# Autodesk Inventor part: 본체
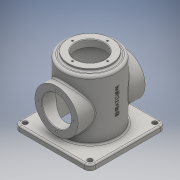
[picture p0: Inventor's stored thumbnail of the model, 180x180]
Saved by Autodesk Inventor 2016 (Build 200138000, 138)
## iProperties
Created: 2019-08
Part Number: 본체
Material: 일반
Document SubType Name: Modeling
Designer: user
Density: 1 g/cm^3
Appearance: 기본값
Author: user
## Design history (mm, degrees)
sketch "스케치1"
  geometry: L1 (-60, -70)-(60, -70); L2 (70, -60)-(70, 60); L3 (60, 70)-(-60, 70); L4 (-70, 60)-(-70, -60); L5 (-70, -70)-(70, 70); L6 (70, -70)-(-70, 70); C1 r 4.5 at (60, 60); C2 r 4.5 at (-60, 60); C3 r 4.5 at (-60, -60); C4 r 4.5 at (60, -60); A1 r 10 centre (-60, 60) between (-60, 70) and (-70, 60); A2 r 10 centre (60, 60) between (70, 60) and (60, 70); A3 r 10 centre (60, -60) between (60, -70) and (70, -60); A4 r 10 centre (-60, -60) between (-70, -60) and (-60, -70); 1 further point
  constraints: 12 end point, 8 centre point, 8 point on circle, 8 point on line, 8 tangent, 6 equal radius, 4 coincident, 2 midpoint, 2 parallel, 1 horizontal, 1 perpendicular
  dimensions: "d0" = 140 distance of L5.end L6.end; "d1" = 140 distance of L6.start L5.end; "d2" = 10 radius of A1; "d3" = 9 diameter of C1
extrude "돌출1" new body sketch "스케치1" distance "d4" = 10; taper "d5" = 0 deg
fillet "모깎기1" dims "d6" = 3
sketch "스케치2"
  geometry: C1 r 50 at (0, 0); 1 further point
  constraints: 1 centre point, 1 coincident
  dimensions: "d7" = 100 diameter of C1
extrude "돌출2" join sketch "스케치2" distance "d8" = 110; taper "d9" = 0 deg
fillet "모깎기2" dims "d10" = 5
node "작업 평면1"
sketch "스케치3"
  geometry: L1 (60, 0)-(-60, 0) reference; L2 (-60, 0)-(-70, 0) reference; C1 r 40 at (0, 60); 2 further points
  constraints: 1 centre point, 1 midpoint, 1 vertical alignment
  dimensions: "d12" = 80 diameter of C1; "d13" = 60 distance from line of L2 C1.centre
extrude "돌출3" join sketch "스케치3" distance "d14" = 124; taper "d15" = 0 deg
sketch "스케치4"
  geometry: C1 r 45 at (0, 0); 1 further point
  constraints: 1 centre point, 1 coincident
  dimensions: "d16" = 90 diameter of C1
extrude "돌출4" cut sketch "스케치4" distance "d17" = 112; taper "d18" = 0 deg
fillet "모깎기3" dims "d19" = 3
sketch "스케치5"
  geometry: L1 (-60, -60)-(60, -60) reference; C1 r 27 at (0, 0); C2 r 40 at (0, 0) reference; 2 further points
  constraints: 1 centre point, 1 concentric, 1 midpoint, 1 vertical alignment
  dimensions: "d20" = 54 diameter of C1
extrude "돌출5" cut sketch "스케치5" stored distance "d21" = 112; taper "d22" = 0 deg
sketch "스케치6"
  geometry: C1 r 40 at (0, 0); 1 further point
  constraints: 1 centre point, 1 coincident
  dimensions: "d23" = 80 diameter of C1
extrude "돌출6" join sketch "스케치6" distance "d24" = 5; taper "d25" = 0 deg
fillet "모깎기4" dims "d26" = 3
sketch "스케치7"
  geometry: C1 r 27 at (0, 0); 1 further point
  constraints: 1 centre point, 1 coincident
  dimensions: "d27" = 54 diameter of C1
extrude "돌출7" cut sketch "스케치7" stored distance "d28" = 15; taper "d29" = 0 deg
chamfer "모따기1" distance "d30" = 1; stored, may be unused: second distance "d31" = 2, angle "d32" = 45 deg
sketch "스케치8" dims "d33" = 65
  geometry: L1 (-60, -60)-(60, -60) reference; C1 r 28 at (0, 0) reference; 4 further points
  constraints: 2 vertical alignment, 1 coincident, 1 midpoint, 2 other
hole "구멍1" sketch "스케치8" at (0, 32.5) diameter "d34" = 3.242; stored, may be unused: countersink angle "d38" = 90 deg, drill point angle "d40" = 118 deg; dims "d35" = 8, "d36" = 4, "d37" = 2, "d39" = 10
sketch "스케치9" dims "d44" = 65
  geometry: 3 further points
  constraints: 2 horizontal alignment, 1 coincident, 2 other
hole "구멍2" sketch "스케치9" at (-32.5, 0) diameter "d45" = 3.242; stored, may be unused: countersink angle "d49" = 90 deg, drill point angle "d51" = 118 deg; dims "d46" = 8, "d47" = 4, "d48" = 2, "d50" = 10
node "작업 평면2"
sketch "스케치10" dims "d0" = 140, "d1" = 140, "d2" = 10, "d3" = 9
  geometry: L1 (-60, 0)-(60, 0) reference; 3 further points
  constraints: 1 midpoint, 1 vertical alignment, 1 other
  dimensions: "d56" = 70 distance from line of L1 point (0, 70)
feature "엠보싱1" sketch "스케치10" dims "d0" = 140, "d1" = 140, "d2" = 10, "d3" = 9, "d57" = 0.5, "d58" = 0
chamfer "모따기2" distance "d59" = 1; stored, may be unused: second distance "d60" = 2, angle "d61" = 45 deg
node "솔리드1"
pattern_circular "원형 패턴1" dims angle "d42" = 360 deg
mirror "대칭1"
pattern_circular "원형 패턴2" dims angle "d53" = 360 deg
other parameters: "d11" = -62
